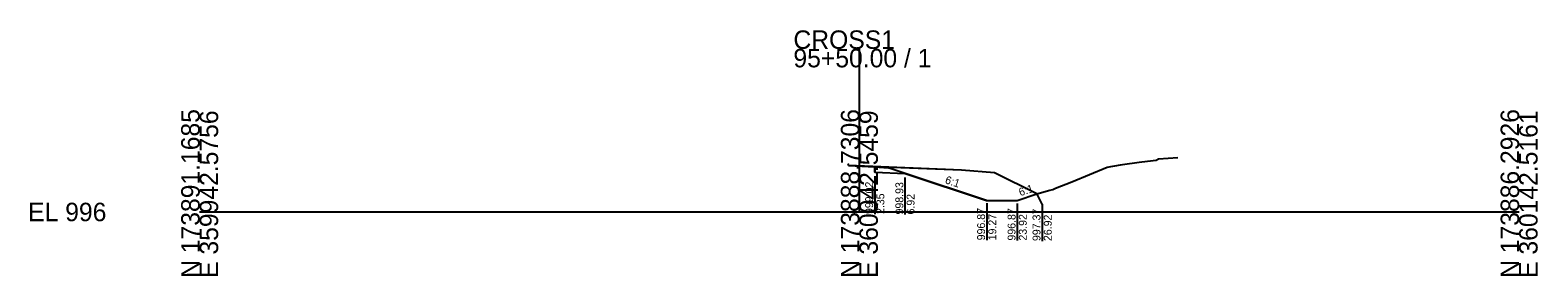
# Model space of a CAD drawing. Extents: x -26 to 1403, y -10 to 11027.
# Drawn here: x -25.7 to 202.8, y 10490.3 to 10527.6 of the extents above; entities that cross this region are included whole.
import ezdxf

# ---------------------------------------------------------------- set-up
doc = ezdxf.new("R2010")
doc.units = 0
for name, color, linetype in [('Default', 7, 'Continuous'), ('P_E_XS_Ground', 7, 'Continuous'), ('P_XS', 7, 'Continuous'), ('P_XS_EAR_CommonGrnd', 7, 'Continuous'), ('P_XS_Lane', 7, 'Continuous'), ('P_XS_Rock', 7, 'Continuous')]:
    doc.layers.add(name, color=color, linetype=linetype)

msp = doc.modelspace()

# ---------------------------------------------------------------- linework, layer by layer
at = {"layer": 'Default'}
for p, q in [((100, 10500), (100, 10524.74)), ((0, 10500), (100, 10500)), ((100, 10500), (200, 10500))]:
    msp.add_line(p, q, dxfattribs=at)
at = {"layer": 'P_E_XS_Ground'}
for p, q in [((145, 10507.85), (145.35, 10508.05)), ((145.35, 10508.05), (148.26, 10508.25)), ((98.18, 10507.28), (98.35, 10507.18)), ((98.35, 10507.03), (98.35, 10507.18)), ((115.5, 10506.34), (98.35, 10507.03)), ((120.5, 10505.94), (115.5, 10506.34)), ((126.92, 10502.73), (120.5, 10505.94)), ((132.18, 10504.56), (137.54, 10506.81)), ((137.54, 10506.81), (139.59, 10507.16)), ((139.59, 10507.16), (139.9, 10507.2)), ((139.9, 10507.2), (142.39, 10507.54)), ((142.39, 10507.54), (142.82, 10507.58)), ((142.82, 10507.58), (145, 10507.85)), ((128.87, 10503.29), (129.31, 10503.42)), ((129.31, 10503.42), (129.75, 10503.63)), ((129.75, 10503.63), (132.18, 10504.56)), ((126.92, 10502.73), (128.87, 10503.29))]:
    msp.add_line(p, q, dxfattribs=at)
at = {"layer": 'P_XS'}
for p, q in [((98.35, 10507.03), (102.35, 10506.87)), ((102.35, 10506.87), (104.35, 10506.71)), ((106.92, 10505.85), (104.35, 10506.71))]:
    msp.add_line(p, q, dxfattribs=at)
at = {"layer": 'P_XS_EAR_CommonGrnd'}
msp.add_lwpolyline([(119.27, 10501.74), (123.92, 10501.74), (126.92, 10502.73), (120.5, 10505.94), (115.5, 10506.34), (102.35, 10506.87), (102.35, 10506.04), (106.92, 10505.85)], close=True, dxfattribs=at)
at = {"layer": 'P_XS_Lane'}
for p, q in [((102.35, 10506.04), (102.35, 10506.87)), ((102.35, 10506.04), (106.92, 10505.85)), ((119.27, 10501.74), (106.92, 10505.85)), ((119.27, 10501.74), (123.92, 10501.74)), ((123.92, 10501.74), (126.92, 10502.73))]:
    msp.add_line(p, q, dxfattribs=at)
at = {"layer": 'P_XS_Rock'}
for p, q in [((102.33, 10505.42), (102.33, 10499.69)), ((106.91, 10505.25), (106.91, 10499.62)), ((119.3, 10501.32), (119.3, 10495.7)), ((123.92, 10501.27), (123.92, 10495.66)), ((127.7, 10501.2), (126.99, 10502.59)), ((127.7, 10501.2), (127.7, 10495.59))]:
    msp.add_line(p, q, dxfattribs=at)

# ---------------------------------------------------------------- texts
at = {"layer": 'Default'}
for s, p in [('CROSS1', (90, 10524.74)), ('95+50.00 / 1', (90, 10521.94)), ('EL 996', (-26, 10498.6))]:
    msp.add_text(s, height=2.8, dxfattribs=at).set_placement(p)
for s, p in [('N 173891.1685', (0, 10490)), ('E 359942.5756', (2.8, 10490)), ('N 173888.7306', (100, 10490)), ('E 360042.5459', (102.8, 10490)), ('N 173886.2926', (200, 10490)), ('E 360142.5161', (202.8, 10490))]:
    msp.add_text(s, height=2.8, rotation=90, dxfattribs=at).set_placement(p)
at = {"layer": 'P_XS_Rock'}
for s, rotation, p in [('999.02', 90, (102.08, 10499.69)), ('998.93', 90, (106.66, 10499.62)), ('6:1', 341.5651, (112.89, 10504.38)), ('6:1', 18.4349, (124.39, 10502.38)), ('2.35', 90, (103.78, 10499.69)), ('6.92', 90, (108.36, 10499.62)), ('996.87', 90, (119.05, 10495.7)), ('19.27', 90, (120.75, 10495.7)), ('996.87', 90, (123.67, 10495.66)), ('23.92', 90, (125.37, 10495.66)), ('997.37', 90, (127.45, 10495.59)), ('26.92', 90, (129.15, 10495.59))]:
    msp.add_text(s, height=1.2, rotation=rotation, dxfattribs=at).set_placement(p)

doc.saveas('drawing.dxf')
